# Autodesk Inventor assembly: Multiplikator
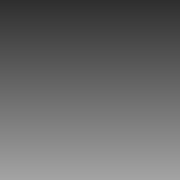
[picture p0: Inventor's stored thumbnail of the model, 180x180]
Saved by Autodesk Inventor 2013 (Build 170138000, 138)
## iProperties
Created: 2015-03
Part Number: Multiplikator
Document SubType Name: Assembly
Designer: Uglješa
Author: Uglješa
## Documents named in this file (1)
- C:\Users\Uglješa\Desktop\Multiplikator.iam
